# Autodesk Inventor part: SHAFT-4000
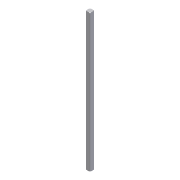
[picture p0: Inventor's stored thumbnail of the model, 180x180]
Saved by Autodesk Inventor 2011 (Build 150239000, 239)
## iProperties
Created: 2007-12
Part Number: SHAFT-4000
Document SubType Name: Modeling
Density: 1 g/cm^3
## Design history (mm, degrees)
feature "Base1"
workaxis "Work Axis1"
  workplane "Work Plane1"
  workplane "Work Plane2"
workplane "Work Plane3"
body "Solid1"
